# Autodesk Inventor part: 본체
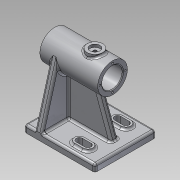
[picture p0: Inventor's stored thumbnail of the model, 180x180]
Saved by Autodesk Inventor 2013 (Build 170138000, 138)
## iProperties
Created: 2019-10
Part Number: 본체
Material: 알루미늄 6061
Document SubType Name: Modeling
Designer: hana-cad17
Density: 2.71 g/cm^3
Mass: 589.796 g
Surface Area: 542.508 cm^2
Volume: 217.637 cm^3
Author: hana-cad17
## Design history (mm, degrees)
sketch "스케치1"
  geometry: L1 (-50, 43)-(50, 43); L2 (50, 43)-(50, -43); L3 (50, -43)-(-50, -43); L4 (-50, -43)-(-50, 43); 3 further points
  constraints: 8 end point, 2 midpoint, 2 parallel, 1 horizontal, 1 horizontal alignment, 1 perpendicular, 1 vertical alignment
  dimensions: "d0" = 100 distance of L1.start L1.end; "d2" = 86 distance of L3.end L1.start
extrude "돌출1" new body sketch "스케치1" distance "d3" = 10; taper "d4" = 0 deg
sketch "스케치2"
  geometry: L1 (-32, 86)-(50, 86); L2 (50, 0)-(-50, 0) reference; L3 (-32, 86)-(-32, 107); L4 (-32, 107)-(50, 107); L5 (50, 107)-(50, 86); L6 (50, 0)-(50, 10) reference; 2 further points
  constraints: 8 end point, 2 perpendicular, 1 horizontal, 1 midpoint, 1 parallel, 1 vertical alignment
  dimensions: "d5" = 82 distance of L1.start L1.end; "d7" = 86 distance from line of L1.end L2; "d8" = 42 diameter of L4 L1
revolve "회전1" sketch "스케치2" stored, may be unused: angle "d9" = 90 deg
sketch "스케치4"
  geometry: L1 (50, 65)-(50, 107) reference; L2 (-32, 65)-(-32, 107) reference; L3 (-32, 86)-(50, 86); L4 (-32, 100.5)-(30, 100.5); L5 (30, 100.5)-(30, 97.5); L6 (30, 97.5)-(50, 97.5); 1 further point
  constraints: 8 end point, 2 midpoint, 2 parallel, 2 point on line, 1 perpendicular
  dimensions: "d11" = 23 diameter of L6 L3; "d13" = 29 diameter of L4 L3; "d14" = 62 distance of L4.start L4.end
revolve "회전2" sketch "스케치4" stored, may be unused: angle "d15" = 90 deg
node "작업 평면1"
sketch "스케치6"
  geometry: L1 (0, 86)-(10, 86) reference; L2 (10, 86)-(10, 0) reference; L3 (10, 0)-(0, 0) reference; L4 (0, 0)-(0, 86) reference; L5 (10, 86)-(91.642, 63.228); L6 (10, 0)-(91.642, 22.772); C1 r 11.5 at (86, 43) reference; A1 r 21 centre (86, 43) between (91.642, 63.228) and (91.642, 22.772) reference; 1 further point
  constraints: 4 end point, 2 point on circle, 2 tangent
extrude "돌출2" join sketch "스케치6" distance "d19" = 10; taper "d20" = 0 deg
sketch "스케치7"
  geometry: L1 (50, 97.5)-(30, 97.5) reference; L2 (30, 97.5)-(30, 100.5) reference; L3 (30, 100.5)-(-32, 100.5) reference; L4 (-32, 100.5)-(-32, 107) reference; L5 (-32, 107)-(50, 107) reference; L6 (50, 107)-(50, 97.5) reference; L7 (-50, 0)-(-50, 10) reference; L8 (-50, 10)-(25, 10) reference; L9 (25, 10)-(25, 65) reference; L10 (25, 65)-(-32, 65) reference; L11 (-32, 65)-(-32, 71.5) reference; L12 (-32, 71.5)-(30, 71.5) reference; L13 (30, 71.5)-(30, 74.5) reference; L14 (30, 74.5)-(50, 74.5) reference; L15 (50, 74.5)-(50, 65) reference; L16 (50, 65)-(35, 65) reference; L17 (35, 65)-(35, 10) reference; L18 (35, 10)-(50, 10) reference; L19 (50, 10)-(50, 0) reference; L20 (50, 0)-(-50, 0) reference; L21 (-35, 10)-(-14.982, 65); 1 further point
  constraints: 2 end point, 2 point on line
  dimensions: "d21" = 70 deg angle of L21 L8; "d22" = 15 distance of L7.end L21.start
feature "리브1" sketch "스케치7" dims "d23" = 1, "d24" = 10, "d25" = 0, "d26" = 0, "d27" = 1, "d28" = 1
sketch "스케치8"
  geometry: L1 (50, -43)-(50, 43) reference; L2 (24, 20)-(12, 20); L3 (24, 34)-(12, 34); A1 r 7 centre (24, 27) between (24, 20) and (24, 34); A2 r 7 centre (12, 27) between (12, 34) and (12, 20); 1 further point
  constraints: 4 end point, 4 point on circle, 4 tangent, 2 centre point, 1 equal radius, 1 horizontal alignment
  dimensions: "d29" = 27 vertical distance of A1.centre point (0, 0); "d30" = 14 diameter of A1; "d31" = 12 distance of A2.centre A1.centre; "d32" = 26 distance from line of A1.centre L1
extrude "돌출3" join sketch "스케치8" distance "d33" = 3; taper "d34" = 0 deg
sketch "스케치9"
  geometry: L1 (24, 34)-(12, 34) reference; L2 (12, 20)-(24, 20) reference; L3 (12, 31.5)-(24, 31.5); L4 (24, 22.5)-(12, 22.5); A1 r 7 centre (24, 27) between (24, 20) and (24, 34) reference; A2 r 7 centre (12, 27) between (12, 34) and (12, 20) reference; A3 r 4.5 centre (24, 27) between (24, 22.5) and (24, 31.5); A4 r 4.5 centre (12, 27) between (12, 31.5) and (12, 22.5); 1 further point
  constraints: 4 end point, 4 point on circle, 2 centre point, 3 other
  dimensions: "d35" = 4.5 radius of A3
extrude "돌출4" cut sketch "스케치9" stored distance "d38" = 10; taper "d39" = 0 deg
node "작업 평면2"
sketch "스케치10"
  geometry: L1 (-32, -21)-(-32, 21) reference; C1 r 11 at (-7, 0); 1 further point
  constraints: 1 centre point, 1 horizontal alignment
  dimensions: "d41" = 22 diameter of C1; "d43" = 25 distance from line of L1 C1.centre
extrude "돌출5" join sketch "스케치10" stored distance "d44" = 10; taper "d45" = 0 deg
sketch "스케치11"
  geometry: C1 r 11 at (0, 0) reference; C2 r 7 at (0, 0); 1 further point
  constraints: 1 centre point, 1 coincident
  dimensions: "d46" = 14 diameter of C2
extrude "돌출6" cut sketch "스케치11" distance "d48" = 4; taper "d49" = 0 deg
sketch "스케치12"
  geometry: 2 further points
  constraints: 1 horizontal alignment
hole "구멍1" sketch "스케치12" at (0, 0) diameter "d50" = 4.917; stored, may be unused: countersink angle "d54" = 90 deg, drill point angle "d56" = 118 deg; dims "d51" = 6, "d52" = 4, "d53" = 2, "d55" = 8
sketch "스케치13"
  geometry: C1 r 11.5 at (0, 0) reference; 2 further points
  constraints: 1 vertical alignment
  dimensions: "d57" = 18 distance of point (0, -18) C1.centre
hole "구멍2" sketch "스케치13" at (0, -18) diameter "d58" = 2.459; stored, may be unused: countersink angle "d62" = 90 deg, drill point angle "d64" = 118 deg; dims "d59" = 8, "d60" = 4, "d61" = 2, "d63" = 10
sketch "스케치14"
  geometry: C1 r 14.5 at (0, 0) reference; 2 further points
  constraints: 1 vertical alignment
  dimensions: "d68" = 18 distance of C1.centre point (0, 18)
hole "구멍3" sketch "스케치14" at (0, 18) diameter "d69" = 2.459; stored, may be unused: countersink angle "d73" = 90 deg, drill point angle "d75" = 118 deg; dims "d70" = 8, "d71" = 4, "d72" = 2, "d74" = 10
fillet "모깎기1" dims "d79" = 3
fillet "모깎기2" dims "d80" = 3
fillet "모깎기3" dims "d81" = 3
fillet "모깎기4" dims "d82" = 3
fillet "모깎기5" dims "d83" = 3
fillet "모깎기6" dims "d84" = 3
fillet "모깎기7" dims "d85" = 3
chamfer "모따기1" distance "d86" = 1; stored, may be unused: second distance "d87" = 2, angle "d88" = 45 deg
node "작업 평면3"
sketch "스케치16"
  geometry: L1 (-50, 40)-(-50, -40) reference; 2 further points
  constraints: 1 horizontal alignment, 1 other
  dimensions: "d90" = 7 distance from line of point (-43, 0) L1
feature "엠보싱1" sketch "스케치16" dims "d0" = 100, "d2" = 86, "d91" = 0.5, "d92" = 0
fillet "모깎기8" dims "d93" = 3
node "솔리드1"
mirror "대칭1"
pattern_circular "원형 패턴1" dims angle "d66" = 360 deg
pattern_circular "원형 패턴2" dims angle "d77" = 360 deg
node "투영된 루프1"
node "절단 모서리 투영1"
node "절단 모서리 투영2"
other parameters: "d18" = -15, "d89" = 15
